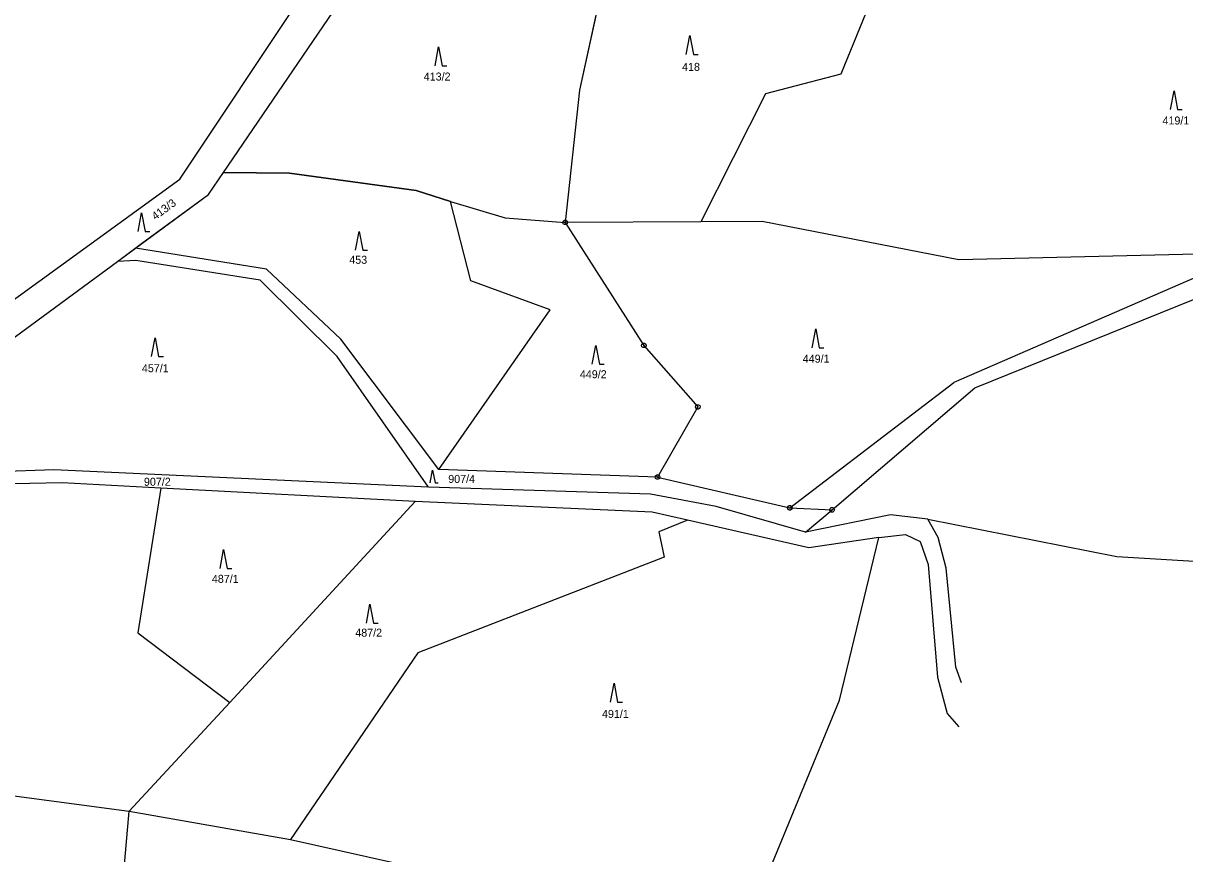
# Model space of a CAD drawing. Extents: x -580551 to -575069, y -1073031 to -1067931.
# Drawn here: x -577624.4 to -577377.7, y -1070436.8 to -1070260.5 of the extents above; entities that cross this region are included whole.
import ezdxf

# ---------------------------------------------------------------- set-up
doc = ezdxf.new("R2010")
doc.units = 0
for name, color, linetype in [('Druh pozemku', 7, 'Continuous'), ('Geodetické body', 7, 'Continuous'), ('Hranice z DKM', 7, 'Continuous'), ('Parcela', 7, 'Continuous'), ('Parcelní číslo', 7, 'Continuous')]:
    doc.layers.add(name, color=color, linetype=linetype)

msp = doc.modelspace()

# ---------------------------------------------------------------- linework, layer by layer
at = {"layer": 'Druh pozemku'}
for points in [[(-577483.57, -1070267.13), (-577482.82, -1070263.13), (-577482.07, -1070267.13), (-577481.07, -1070267.13)], [(-577536.92, -1070269.54), (-577536.17, -1070265.54), (-577535.42, -1070269.54), (-577534.42, -1070269.54)], [(-577380.71, -1070278.84), (-577379.96, -1070274.84), (-577379.21, -1070278.84), (-577378.21, -1070278.84)], [(-577600.03, -1070304.73), (-577599.28, -1070300.73), (-577598.53, -1070304.73), (-577597.53, -1070304.73)], [(-577553.8, -1070308.68), (-577553.05, -1070304.68), (-577552.3, -1070308.68), (-577551.3, -1070308.68)], [(-577456.83, -1070329.41), (-577456.08, -1070325.41), (-577455.33, -1070329.41), (-577454.33, -1070329.41)], [(-577597.15, -1070331.28), (-577596.4, -1070327.28), (-577595.65, -1070331.28), (-577594.65, -1070331.28)], [(-577503.53, -1070332.91), (-577502.78, -1070328.91), (-577502.03, -1070332.91), (-577501.03, -1070332.91)], [(-577537.952, -1070358.05), (-577537.45, -1070355.37), (-577536.948, -1070358.05), (-577536.278, -1070358.05)], [(-577582.6, -1070376.25), (-577581.85, -1070372.25), (-577581.1, -1070376.25), (-577580.1, -1070376.25)], [(-577551.51, -1070387.85), (-577550.76, -1070383.85), (-577550.01, -1070387.85), (-577549.01, -1070387.85)], [(-577499.65, -1070404.6), (-577498.9, -1070400.6), (-577498.15, -1070404.6), (-577497.15, -1070404.6)]]:
    msp.add_lwpolyline(points, dxfattribs=at)
at = {"layer": 'Geodetické body'}
for p, q in [((-577509.41, -1070302.79), (-577509.17, -1070302.79)), ((-577492.72, -1070328.91), (-577492.48, -1070328.91)), ((-577481.25, -1070341.96), (-577481.01, -1070341.96)), ((-577489.8, -1070356.86), (-577489.56, -1070356.86)), ((-577461.69, -1070363.39), (-577461.45, -1070363.39)), ((-577452.74, -1070363.82), (-577452.5, -1070363.82))]:
    msp.add_line(p, q, dxfattribs=at)
for points in [[(-577509.14, -1070302.31), (-577508.89, -1070302.49), (-577508.79, -1070302.78), (-577508.89, -1070303.07), (-577509.14, -1070303.25), (-577509.45, -1070303.25), (-577509.7, -1070303.07), (-577509.8, -1070302.78), (-577509.7, -1070302.49), (-577509.45, -1070302.31)], [(-577492.45, -1070328.43), (-577492.2, -1070328.61), (-577492.1, -1070328.9), (-577492.2, -1070329.19), (-577492.45, -1070329.37), (-577492.76, -1070329.37), (-577493.01, -1070329.19), (-577493.11, -1070328.9), (-577493.01, -1070328.61), (-577492.76, -1070328.43)], [(-577480.98, -1070341.48), (-577480.73, -1070341.66), (-577480.63, -1070341.95), (-577480.73, -1070342.24), (-577480.98, -1070342.42), (-577481.29, -1070342.42), (-577481.54, -1070342.24), (-577481.64, -1070341.95), (-577481.54, -1070341.66), (-577481.29, -1070341.48)], [(-577489.53, -1070356.38), (-577489.28, -1070356.56), (-577489.18, -1070356.85), (-577489.28, -1070357.14), (-577489.53, -1070357.32), (-577489.84, -1070357.32), (-577490.09, -1070357.14), (-577490.19, -1070356.85), (-577490.09, -1070356.56), (-577489.84, -1070356.38)], [(-577461.42, -1070362.91), (-577461.17, -1070363.09), (-577461.07, -1070363.38), (-577461.17, -1070363.67), (-577461.42, -1070363.85), (-577461.73, -1070363.85), (-577461.98, -1070363.67), (-577462.08, -1070363.38), (-577461.98, -1070363.09), (-577461.73, -1070362.91)], [(-577452.47, -1070363.34), (-577452.22, -1070363.52), (-577452.12, -1070363.81), (-577452.22, -1070364.1), (-577452.47, -1070364.28), (-577452.78, -1070364.28), (-577453.03, -1070364.1), (-577453.13, -1070363.81), (-577453.03, -1070363.52), (-577452.78, -1070363.34)]]:
    msp.add_lwpolyline(points, close=True, dxfattribs=at)
at = {"layer": 'Hranice z DKM'}
for p, q in [((-577591.12, -1070293.63), (-577551.94, -1070234.66)), ((-577667.04, -1070348.51), (-577591.12, -1070293.63)), ((-577659.47, -1070351.44), (-577604.41, -1070311.07))]:
    msp.add_line(p, q, dxfattribs=at)
for points in [[(-577499.81, -1070245.09), (-577506.24, -1070274.73), (-577509.29, -1070302.79)], [(-577604.41, -1070311.07), (-577599.265, -1070307.296), (-577585.09, -1070296.89), (-577581.85, -1070292.21)], [(-577581.85, -1070292.21), (-577567.82, -1070292.33), (-577540.94, -1070295.98), (-577533.63, -1070298.33), (-577522.07, -1070301.8), (-577509.29, -1070302.79)]]:
    msp.add_lwpolyline(points, dxfattribs=at)
at = {"layer": 'Parcela'}
for p, q in [((-577591.12, -1070293.63), (-577551.94, -1070234.66)), ((-577581.85, -1070292.21), (-577545.93, -1070239.47)), ((-577499.81, -1070245.09), (-577506.24, -1070274.73)), ((-577442.96, -1070252.28), (-577450.77, -1070271.31)), ((-577450.77, -1070271.31), (-577466.73, -1070275.48)), ((-577506.24, -1070274.73), (-577509.29, -1070302.79)), ((-577466.73, -1070275.48), (-577480.47, -1070302.65)), ((-577667.04, -1070348.51), (-577591.12, -1070293.63)), ((-577585.09, -1070296.89), (-577581.85, -1070292.21)), ((-577567.82, -1070292.33), (-577581.85, -1070292.21)), ((-577540.94, -1070295.98), (-577567.82, -1070292.33)), ((-577600.55, -1070308.23), (-577585.09, -1070296.89)), ((-577533.63, -1070298.33), (-577540.94, -1070295.98)), ((-577529.35, -1070315.19), (-577533.63, -1070298.33)), ((-577533.63, -1070298.33), (-577522.07, -1070301.8)), ((-577522.07, -1070301.8), (-577509.29, -1070302.79)), ((-577480.47, -1070302.65), (-577509.29, -1070302.79)), ((-577509.29, -1070302.79), (-577492.6, -1070328.91)), ((-577467.46, -1070302.58), (-577480.47, -1070302.65)), ((-577425.71, -1070310.7), (-577467.46, -1070302.58)), ((-577604.41, -1070311.07), (-577600.55, -1070308.23)), ((-577572.72, -1070312.68), (-577600.55, -1070308.23)), ((-577363.55, -1070309.29), (-577426.74, -1070336.77)), ((-577363.55, -1070309.29), (-577425.71, -1070310.7)), ((-577659.47, -1070351.44), (-577604.41, -1070311.07)), ((-577600.51, -1070310.85), (-577604.41, -1070311.07)), ((-577574.09, -1070315.04), (-577600.51, -1070310.85)), ((-577556.95, -1070327.55), (-577572.72, -1070312.68)), ((-577557.76, -1070331.24), (-577574.09, -1070315.04)), ((-577512.47, -1070321.35), (-577529.35, -1070315.19)), ((-577422.28, -1070337.88), (-577368.27, -1070316.1)), ((-577536.13, -1070355.22), (-577512.47, -1070321.35)), ((-577536.13, -1070355.22), (-577556.95, -1070327.55)), ((-577492.6, -1070328.91), (-577481.13, -1070341.96)), ((-577538.32, -1070358.99), (-577557.76, -1070331.24)), ((-577461.57, -1070363.39), (-577426.74, -1070336.77)), ((-577452.62, -1070363.82), (-577422.28, -1070337.88)), ((-577481.13, -1070341.96), (-577489.68, -1070356.86)), ((-577617.91, -1070355.29), (-577643.65, -1070356.18)), ((-577538.32, -1070358.99), (-577617.91, -1070355.29)), ((-577489.68, -1070356.86), (-577536.13, -1070355.22)), ((-577616.11, -1070358.07), (-577645.68, -1070358.7)), ((-577595.2, -1070359.17), (-577616.11, -1070358.07)), ((-577489.68, -1070356.86), (-577461.57, -1070363.39)), ((-577595.2, -1070359.17), (-577600.08, -1070389.89)), ((-577541.14, -1070362.03), (-577595.2, -1070359.17)), ((-577491.14, -1070360.47), (-577538.32, -1070358.99)), ((-577477.23, -1070363.06), (-577491.14, -1070360.47)), ((-577580.55, -1070404.68), (-577541.14, -1070362.03)), ((-577490.84, -1070364.31), (-577541.14, -1070362.03)), ((-577458.28, -1070368.55), (-577477.23, -1070363.06)), ((-577461.57, -1070363.39), (-577452.62, -1070363.82)), ((-577483.3, -1070366.01), (-577490.84, -1070364.31)), ((-577483.3, -1070366.01), (-577489.41, -1070368.5)), ((-577457.57, -1070371.84), (-577483.3, -1070366.01)), ((-577458.28, -1070368.55), (-577452.62, -1070363.82)), ((-577440.22, -1070364.84), (-577458.28, -1070368.55)), ((-577432.26, -1070365.79), (-577440.22, -1070364.84)), ((-577430.04, -1070369.68), (-577432.26, -1070365.79)), ((-577432.26, -1070365.79), (-577392.14, -1070373.71)), ((-577489.41, -1070368.5), (-577488.25, -1070373.87)), ((-577442.67, -1070369.7), (-577457.57, -1070371.84)), ((-577451.04, -1070404.2), (-577442.67, -1070369.7)), ((-577442.67, -1070369.7), (-577437.02, -1070369.06)), ((-577437.02, -1070369.06), (-577433.91, -1070370.53)), ((-577433.91, -1070370.53), (-577432.2, -1070375.44)), ((-577428.35, -1070376.19), (-577430.04, -1070369.68)), ((-577488.25, -1070373.87), (-577540.62, -1070394.17)), ((-577432.2, -1070375.44), (-577430.2, -1070399.32)), ((-577392.14, -1070373.71), (-577368.33, -1070375.1)), ((-577426.31, -1070397.21), (-577428.35, -1070376.19)), ((-577600.08, -1070389.89), (-577580.55, -1070404.68)), ((-577540.62, -1070394.17), (-577567.64, -1070433.75)), ((-577425.08, -1070400.52), (-577426.31, -1070397.21)), ((-577430.2, -1070399.32), (-577428.13, -1070407.01)), ((-577601.89, -1070427.79), (-577580.55, -1070404.68)), ((-577470.88, -1070452.36), (-577451.04, -1070404.2)), ((-577428.13, -1070407.01), (-577425.67, -1070409.86)), ((-577627.94, -1070424.32), (-577601.89, -1070427.79)), ((-577607.92, -1070496.9), (-577601.89, -1070427.79)), ((-577601.89, -1070427.79), (-577567.64, -1070433.75)), ((-577567.64, -1070433.75), (-577509.21, -1070446.82))]:
    msp.add_line(p, q, dxfattribs=at)

# ---------------------------------------------------------------- texts
at = {"layer": 'Parcelní číslo'}
for s, p in [('418', (-577484.465, -1070270.62)), ('413/2', (-577539.334, -1070272.67)), ('419/1', (-577382.415, -1070282)), ('453', (-577555.152, -1070311.57)), ('449/1', (-577458.832, -1070332.56)), ('457/1', (-577599.208, -1070334.59)), ('449/2', (-577506.174, -1070335.86)), ('907/2', (-577598.772, -1070358.69)), ('907/4', (-577534.137, -1070358.09)), ('487/1', (-577584.34, -1070379.3)), ('487/2', (-577553.882, -1070390.73)), ('491/1', (-577501.475, -1070407.97))]:
    msp.add_text(s, height=1.7, dxfattribs=at).set_placement(p)
msp.add_text('413/3', height=1.7, rotation=36.32552, dxfattribs=at).set_placement((-577596.357, -1070302.374))

doc.saveas('drawing.dxf')
